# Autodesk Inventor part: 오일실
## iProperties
IsCustomPart: 0
Created: 2009-02
Part Number: 오일실
Material: 고무
Description: 오일-실
Document SubType Name: Modeling
Standard: KS B 2804
Designer: KYOUNG IL JANG
Standards Organization: KS
Language: ko-KR
Size Designation: D - 20 32 8
Categories: <MemberInstance><Categories><Category DisplayName="샤프트 부품" InternalName="7f7aeb1f-a693-4053-b835-cee3144e0d98" Mnemonic="SHFT"><Category DisplayName="실링" Intern
Density: 0.93 g/cm^3
Mass: 2.19344 g
Surface Area: 31.4782 cm^2
Volume: 2.35853 cm^3
Author: KYOUNG IL JANG
